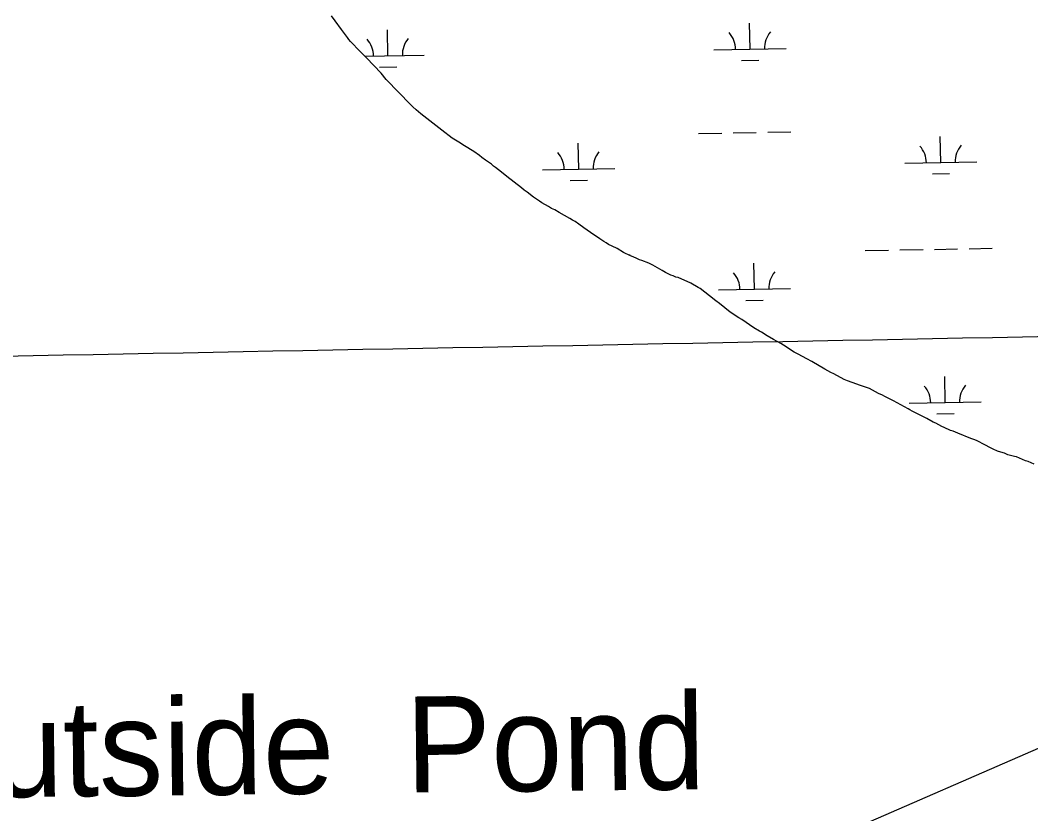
# Model space of a CAD drawing. Extents: x 3957609 to 3995875, y 234277 to 260273.
# Drawn here: x 3969955 to 3971355, y 248308 to 249408 of the extents above; entities that cross this region are included whole.
import ezdxf

# ---------------------------------------------------------------- set-up
doc = ezdxf.new("R2010")
doc.units = 0
for name, color, linetype in [('V-GRID-MAJR', 7, 'Continuous'), ('V-RIVR-IDEN', 7, 'Continuous'), ('V-TOPO-SHOR', 7, 'Continuous'), ('V-UTIL-LINE', 7, 'Continuous'), ('V-WETL-SWMP', 7, 'Continuous')]:
    doc.layers.add(name, color=color, linetype=linetype)

msp = doc.modelspace()

# ---------------------------------------------------------------- linework, layer by layer
at = {"layer": 'V-GRID-MAJR'}
msp.add_spline([(3961703.892, 248787.859), (3967022.571, 248887.277), (3972341.236, 248987.469), (3977659.886, 249088.434), (3982978.522, 249190.173), (3988297.143, 249292.685), (3993615.748, 249395.971), (3993615.749, 249395.971)], degree=3, dxfattribs=at)
at = {"layer": 'V-TOPO-SHOR'}
for points in [[(3971114.127, 248903.079), (3971101.565, 248907.625), (3971096.762, 248909.722), (3971082.217, 248917.259), (3971078.353, 248919.499), (3971069.997, 248923.831), (3971051.755, 248934.54), (3971045.105, 248938.222), (3971033.036, 248944.477), (3971027.626, 248947.518), (3971021.136, 248951.51), (3971016.505, 248954.694), (3971009.087, 248959.325), (3970998.726, 248965.086), (3970989.916, 248970.204), (3970982.346, 248974.99), (3970979.252, 248976.594), (3970971.523, 248981.226), (3970965.504, 248985.367), (3970960.715, 248988.4), (3970954.852, 248992.695), (3970950.987, 248994.933), (3970938.632, 249002.906), (3970923.839, 249014.813), (3970918.903, 249018.471), (3970910.124, 249025.77), (3970897.17, 249035.623), (3970894.385, 249037.067), (3970884.182, 249042.984), (3970866.522, 249050.723), (3970863.573, 249051.546), (3970859.853, 249053.158), (3970856.753, 249054.295), (3970852.726, 249056.226), (3970849.167, 249057.991), (3970844.686, 249060.707), (3970831.698, 249068.068), (3970825.967, 249070.8), (3970816.51, 249074.367), (3970813.098, 249075.508), (3970809.225, 249077.279), (3970804.273, 249079.69), (3970800.707, 249081.144), (3970791.108, 249085.805), (3970781.986, 249090.925), (3970775.175, 249094.298), (3970770.378, 249096.862), (3970766.981, 249098.939), (3970763.577, 249100.702), (3970758.332, 249104.678), (3970745.206, 249113.285), (3970736.105, 249119.966), (3970729.005, 249124.746), (3970723.76, 249128.563), (3970720.045, 249130.489), (3970716.338, 249132.881), (3970701.959, 249141.04), (3970695.618, 249144.562), (3970691.283, 249146.651), (3970687.111, 249149.207), (3970677.831, 249154.329), (3970674.434, 249156.562), (3970666.098, 249162.296), (3970657.314, 249169.284), (3970653.454, 249171.834), (3970649.448, 249175.166), (3970629.255, 249190.892), (3970626.635, 249193.112), (3970617.694, 249199.946), (3970613.534, 249203.436), (3970610.913, 249205.345), (3970607.835, 249208.04), (3970599.497, 249213.775), (3970594.406, 249217.432), (3970591.479, 249219.814), (3970583.453, 249225.387), (3970570.633, 249233.523), (3970562.594, 249238.318), (3970553.639, 249244.216), (3970538.985, 249255.029), (3970526.498, 249264.721), (3970518.333, 249271.389), (3970509.852, 249277.904), (3970503.536, 249283.138), (3970499.076, 249287.257), (3970475.727, 249311.136), (3970465.747, 249321.727), (3970462.058, 249325.366), (3970455.013, 249334.043), (3970434.586, 249355.23), (3970432.44, 249357.755), (3970422.915, 249367.403), (3970416.007, 249374.831), (3970412.779, 249377.995), (3970410.481, 249380.836), (3970408.497, 249383.67), (3970400.082, 249394.705), (3970391.525, 249406.678), (3970386.325, 249413.612)], [(3971359.93, 248792.407), (3971351.871, 248795.796), (3971348.15, 248797.099), (3971335.596, 248802.27), (3971332.645, 248802.936), (3971323.793, 248805.403), (3971318.988, 248807.343), (3971313.709, 248808.668), (3971309.369, 248810.446), (3971303.325, 248813.026), (3971298.529, 248815.434), (3971292.496, 248818.642), (3971287.851, 248820.89), (3971284.914, 248822.648), (3971280.117, 248825.212), (3971276.398, 248826.67), (3971272.208, 248827.978), (3971254.231, 248835.411), (3971247.876, 248837.842), (3971243.997, 248839.144), (3971235.479, 248843.164), (3971232.223, 248844.303), (3971223.715, 248848.95), (3971219.998, 248850.562), (3971211.186, 248855.678), (3971198.496, 248862.098), (3971190.911, 248865.795), (3971187.972, 248867.396), (3971185.346, 248869.149), (3971165.237, 248879.885), (3971153.164, 248885.986), (3971149.762, 248887.905), (3971144.341, 248890.324), (3971131.654, 248896.9), (3971118.008, 248901.93), (3971114.127, 248903.079)]]:
    msp.add_lwpolyline(points, dxfattribs=at)
at = {"layer": 'V-UTIL-LINE'}
msp.add_lwpolyline([(3961767.682, 245361.868), (3961943.705, 245468.964), (3965208.639, 247597.169), (3966396.749, 247622.307), (3967484.854, 247669.667), (3969697.646, 247716.332), (3970569.601, 248052.102), (3971717.759, 248552.062), (3975420.027, 250066.441), (3979384.42, 251663.69), (3984441.626, 253334.756), (3993476.194, 256555.397)], dxfattribs=at)
at = {"layer": 'V-WETL-SWMP'}
for p, q in [((3970966.325, 249367.298), (3970965.671, 249403.292)), ((3970464.5, 249358.174), (3970463.846, 249394.168)), ((3970916.334, 249366.389), (3971016.317, 249368.207)), ((3970432.578, 249357.593), (3970514.492, 249359.083)), ((3970954.608, 249351.652), (3970978.604, 249352.088)), ((3970452.783, 249342.527), (3970476.779, 249342.963)), ((3970895.028, 249250.551), (3970927.023, 249251.133)), ((3970943.02, 249251.424), (3970975.015, 249252.005)), ((3970991.012, 249252.296), (3971023.007, 249252.878)), ((3970728.836, 249201.091), (3970728.181, 249237.085)), ((3971230.661, 249210.216), (3971230.006, 249246.21)), ((3971180.669, 249209.307), (3971280.653, 249211.125)), ((3970678.844, 249200.182), (3970778.828, 249202)), ((3971218.943, 249194.569), (3971242.939, 249195.006)), ((3970717.118, 249185.445), (3970741.114, 249185.881)), ((3970798.398, 249082.265), (3970800.163, 249082.297)), ((3971126.017, 249088.222), (3971158.012, 249088.804)), ((3971174.009, 249089.095), (3971206.004, 249089.677)), ((3971222.002, 249089.968), (3971253.996, 249090.55)), ((3971269.994, 249090.84), (3971301.988, 249091.422)), ((3970972.373, 249034.678), (3970971.719, 249070.672)), ((3970922.382, 249033.769), (3971022.365, 249035.587)), ((3970960.656, 249019.032), (3970984.652, 249019.468)), ((3971236.709, 248877.596), (3971236.054, 248913.59)), ((3971186.717, 248876.687), (3971286.701, 248878.505)), ((3971224.991, 248861.949), (3971248.987, 248862.386))]:
    msp.add_line(p, q, dxfattribs=at)
for points in [[(3970954.853, 248992.694), (3970950.988, 248994.933), (3970938.632, 249002.907), (3970923.839, 249014.814), (3970918.903, 249018.472), (3970910.123, 249025.77), (3970897.171, 249035.624), (3970894.385, 249037.068), (3970884.182, 249042.984), (3970866.522, 249050.724), (3970863.572, 249051.546), (3970859.854, 249053.159), (3970856.752, 249054.295), (3970852.727, 249056.225), (3970849.167, 249057.991), (3970844.685, 249060.707), (3970831.697, 249068.067), (3970825.968, 249070.8), (3970816.51, 249074.367), (3970813.097, 249075.508), (3970809.225, 249077.279), (3970804.272, 249079.689), (3970800.707, 249081.144), (3970791.109, 249085.805), (3970781.986, 249090.926), (3970775.175, 249094.299), (3970770.379, 249096.863), (3970766.98, 249098.939), (3970763.576, 249100.703), (3970758.333, 249104.677), (3970745.207, 249113.286), (3970736.106, 249119.966), (3970729.004, 249124.746), (3970723.759, 249128.564), (3970720.045, 249130.488), (3970716.338, 249132.881), (3970701.958, 249141.04), (3970695.618, 249144.562), (3970691.283, 249146.652), (3970687.111, 249149.207), (3970677.831, 249154.33), (3970674.434, 249156.562), (3970666.099, 249162.296), (3970657.314, 249169.283), (3970653.453, 249171.833), (3970649.449, 249175.165), (3970629.254, 249190.892), (3970626.636, 249193.113), (3970617.693, 249199.946), (3970613.535, 249203.437), (3970610.912, 249205.345), (3970607.834, 249208.04), (3970599.498, 249213.774), (3970594.407, 249217.433), (3970591.479, 249219.814), (3970583.454, 249225.387), (3970570.632, 249233.524), (3970562.595, 249238.318), (3970553.639, 249244.216), (3970538.985, 249255.03), (3970526.498, 249264.721), (3970518.333, 249271.388), (3970509.853, 249277.903), (3970503.537, 249283.139), (3970499.076, 249287.257), (3970475.726, 249311.137), (3970465.747, 249321.727), (3970462.058, 249325.366), (3970455.013, 249334.043), (3970434.586, 249355.23), (3970432.44, 249357.755), (3970422.914, 249367.404), (3970416.007, 249374.831), (3970412.779, 249377.996), (3970410.482, 249380.836), (3970408.496, 249383.671), (3970400.082, 249394.706), (3970391.526, 249406.678), (3970386.326, 249413.613)], [(3971359.929, 248792.406), (3971351.872, 248795.797), (3971348.149, 248797.098), (3971335.596, 248802.269), (3971332.644, 248802.936), (3971323.794, 248805.403), (3971318.989, 248807.343), (3971313.708, 248808.667), (3971309.368, 248810.445), (3971303.326, 248813.027), (3971298.528, 248815.435), (3971292.495, 248818.641), (3971287.85, 248820.891), (3971284.914, 248822.648), (3971280.118, 248825.212), (3971276.398, 248826.669), (3971272.208, 248827.978), (3971254.231, 248835.41), (3971247.875, 248837.841), (3971243.996, 248839.144), (3971235.48, 248843.165), (3971232.223, 248844.304), (3971223.716, 248848.949), (3971219.998, 248850.562), (3971211.186, 248855.678), (3971198.496, 248862.098), (3971190.91, 248865.794), (3971187.971, 248867.396), (3971185.347, 248869.149), (3971165.236, 248879.886), (3971153.164, 248885.986), (3971149.763, 248887.906), (3971144.341, 248890.323), (3971131.653, 248896.899), (3971118.007, 248901.93), (3971114.126, 248903.078), (3971101.565, 248907.625), (3971096.762, 248909.722), (3971082.217, 248917.26), (3971078.352, 248919.499), (3971069.997, 248923.83), (3971051.756, 248934.54), (3971045.106, 248938.222), (3971033.037, 248944.477), (3971027.625, 248947.518), (3971021.135, 248951.51), (3971016.504, 248954.695), (3971009.088, 248959.324), (3970998.727, 248965.086), (3970989.915, 248970.203), (3970982.346, 248974.99), (3970979.251, 248976.594), (3970971.523, 248981.227), (3970965.503, 248985.368), (3970960.715, 248988.4), (3970954.853, 248992.694)]]:
    msp.add_lwpolyline(points, dxfattribs=at)
for centre, start, end in [((3970911.083, 249366.769), 0.269879, 41.813537), ((3971021.551, 249368.777), 140.269876, 181.813534), ((3970409.258, 249357.644), 0.269879, 41.813537), ((3970519.726, 249359.653), 140.269876, 181.813534), ((3970673.593, 249200.562), 0.269879, 41.813537), ((3970784.061, 249202.57), 140.269876, 181.813534), ((3971175.418, 249209.686), 0.269879, 41.813537), ((3971285.886, 249211.695), 140.269876, 181.813534), ((3970917.131, 249034.149), 0.269879, 41.813537), ((3971027.599, 249036.157), 140.269876, 181.813534), ((3971181.466, 248877.066), 0.269879, 41.813537), ((3971291.934, 248879.075), 140.269876, 181.813534)]:
    msp.add_arc(centre, 35.246, start, end, dxfattribs=at)

# ---------------------------------------------------------------- texts
at = {"layer": 'V-RIVR-IDEN'}
msp.add_text('Mann  Outside  Pond ', height=132.99974, rotation=0.658314, dxfattribs=at).set_placement((3969234.145, 248322.683))

doc.saveas('drawing.dxf')
